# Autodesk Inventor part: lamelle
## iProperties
Shininess: 64.0
Length Units: 11269
Angle Units: 11279
Time Units: 11290
Mass Units: 11283
Length Display Precision: 3
Angle Display Precision: 2
Compacted: True
Part Number: lamelle
Document SubType Name: Modeling
Created: 2005-02
Material: Par défaut
Designer: David
Manufacturer: Standard
Standards Organization: Custom
Density: 0.0
Volumn: 0.0
Area: 0.0
PropertySet Name: Model Information
Control State: 0
Master: False
Checked Out: False
Author: David
